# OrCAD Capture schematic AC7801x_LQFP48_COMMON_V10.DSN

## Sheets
1 POWER: size Custom; title: AC7801x_LQFP48_COMMON; rev: 1.0; company: Xinghui.Liu; note: POWER
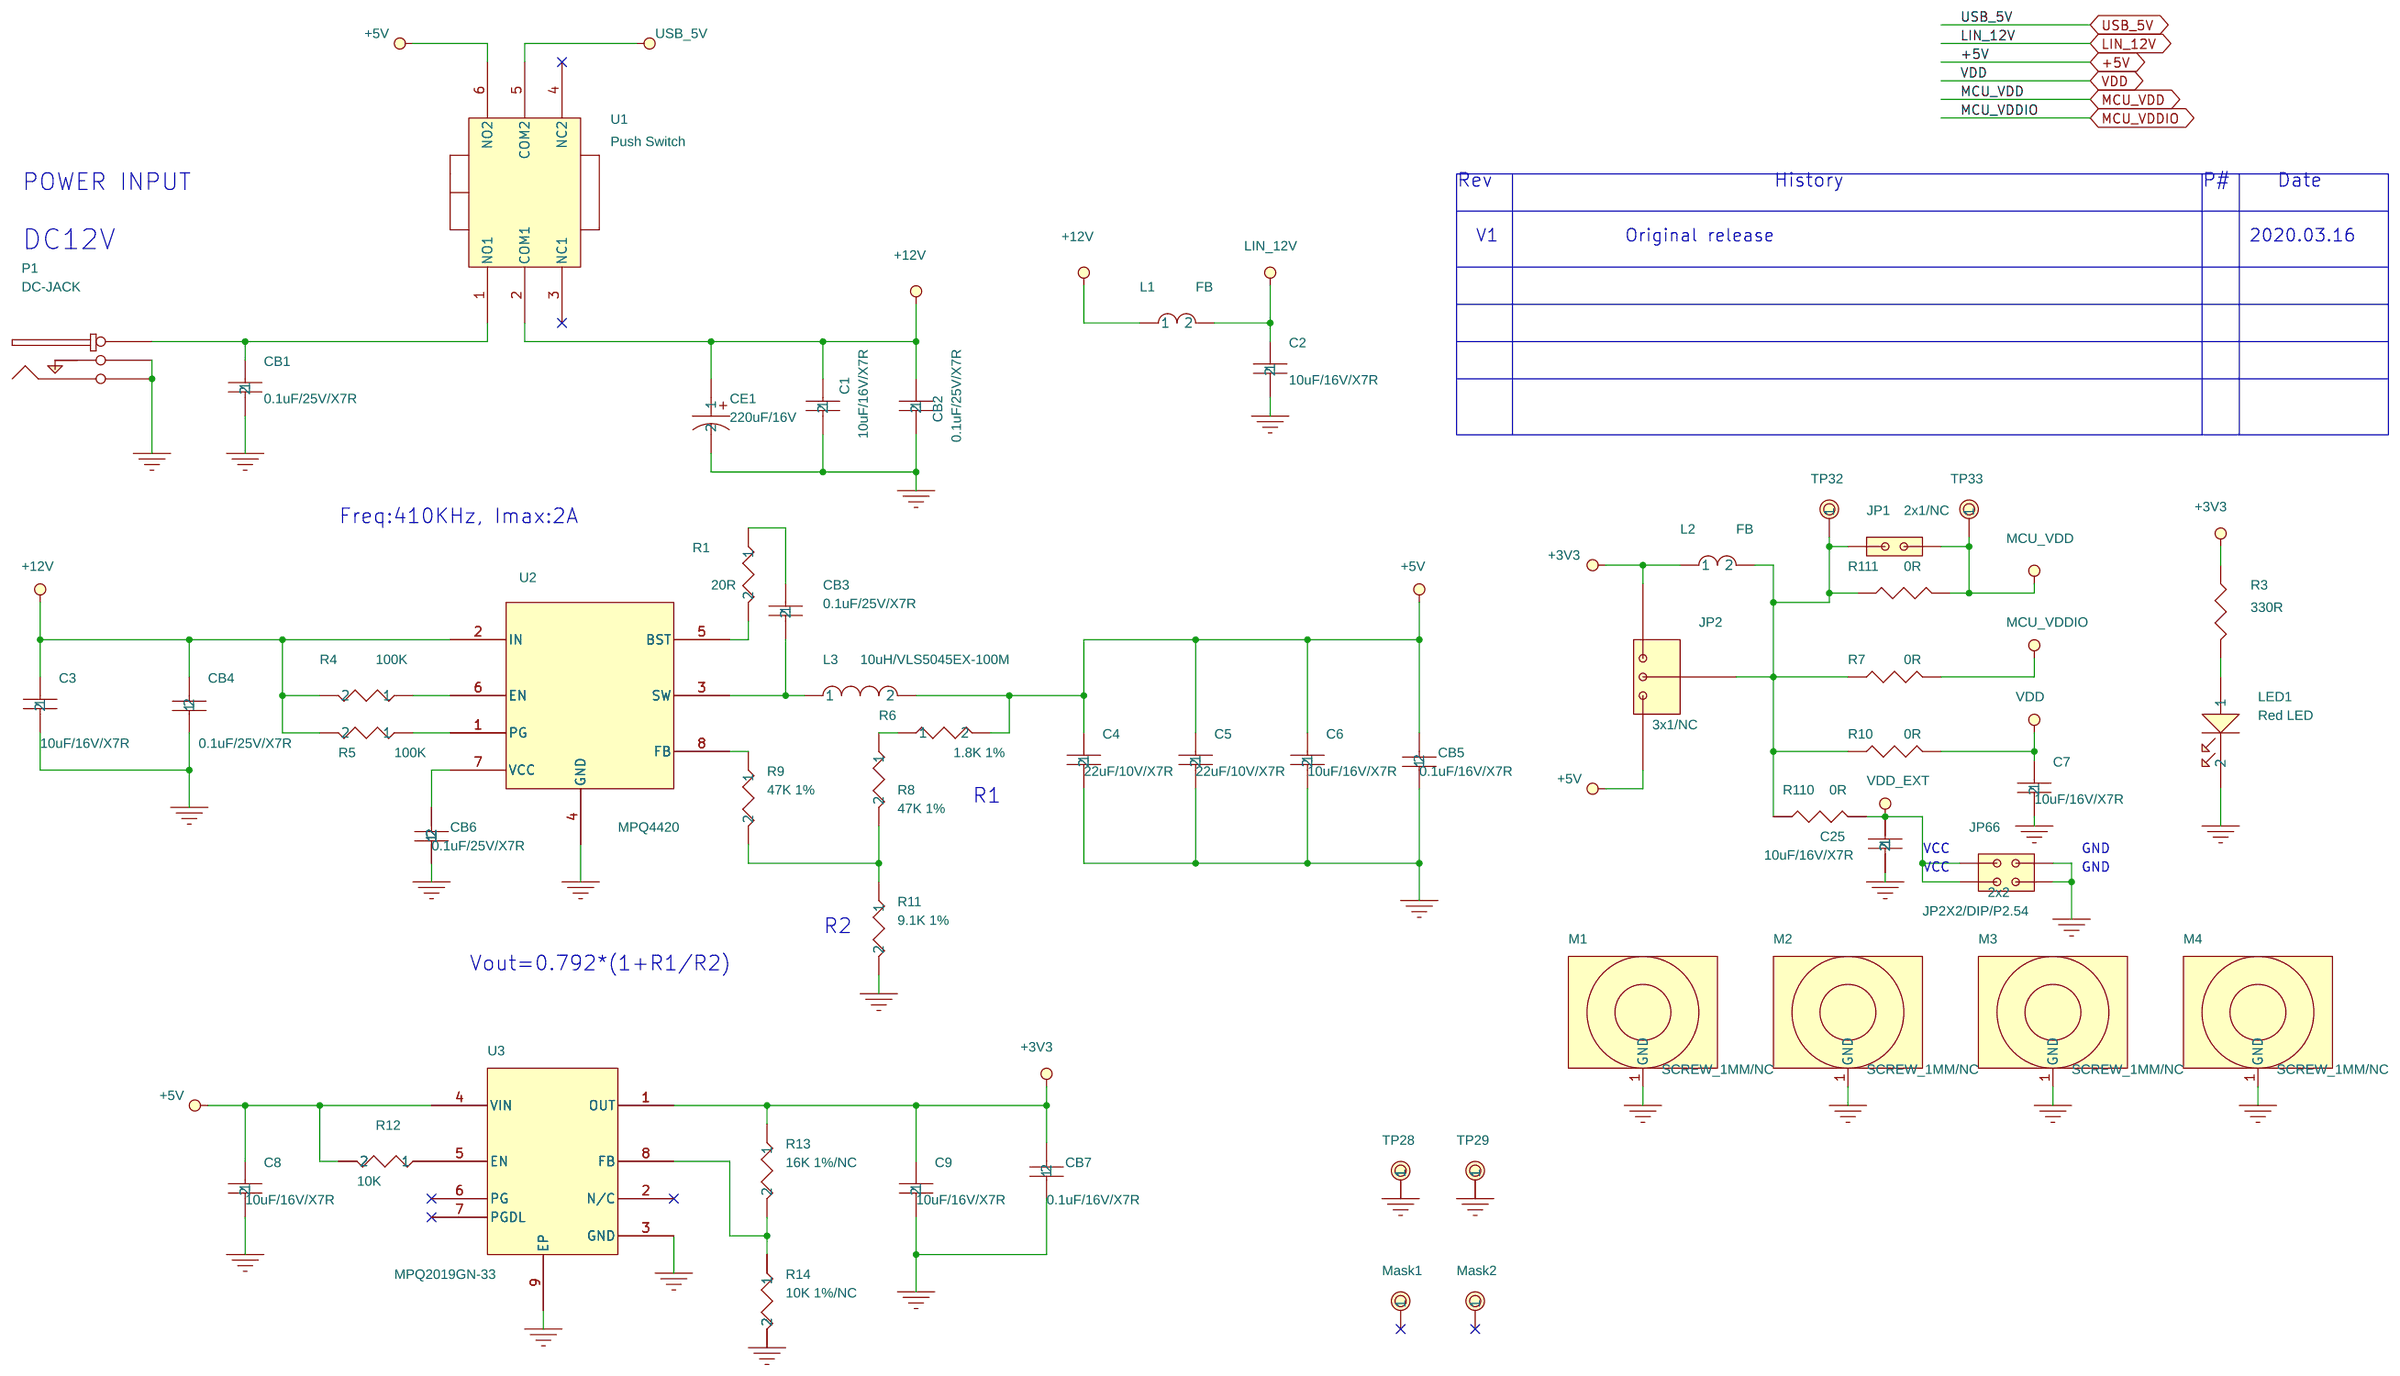
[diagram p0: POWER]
2 SYSTEM: size Custom; note: SYSTEM
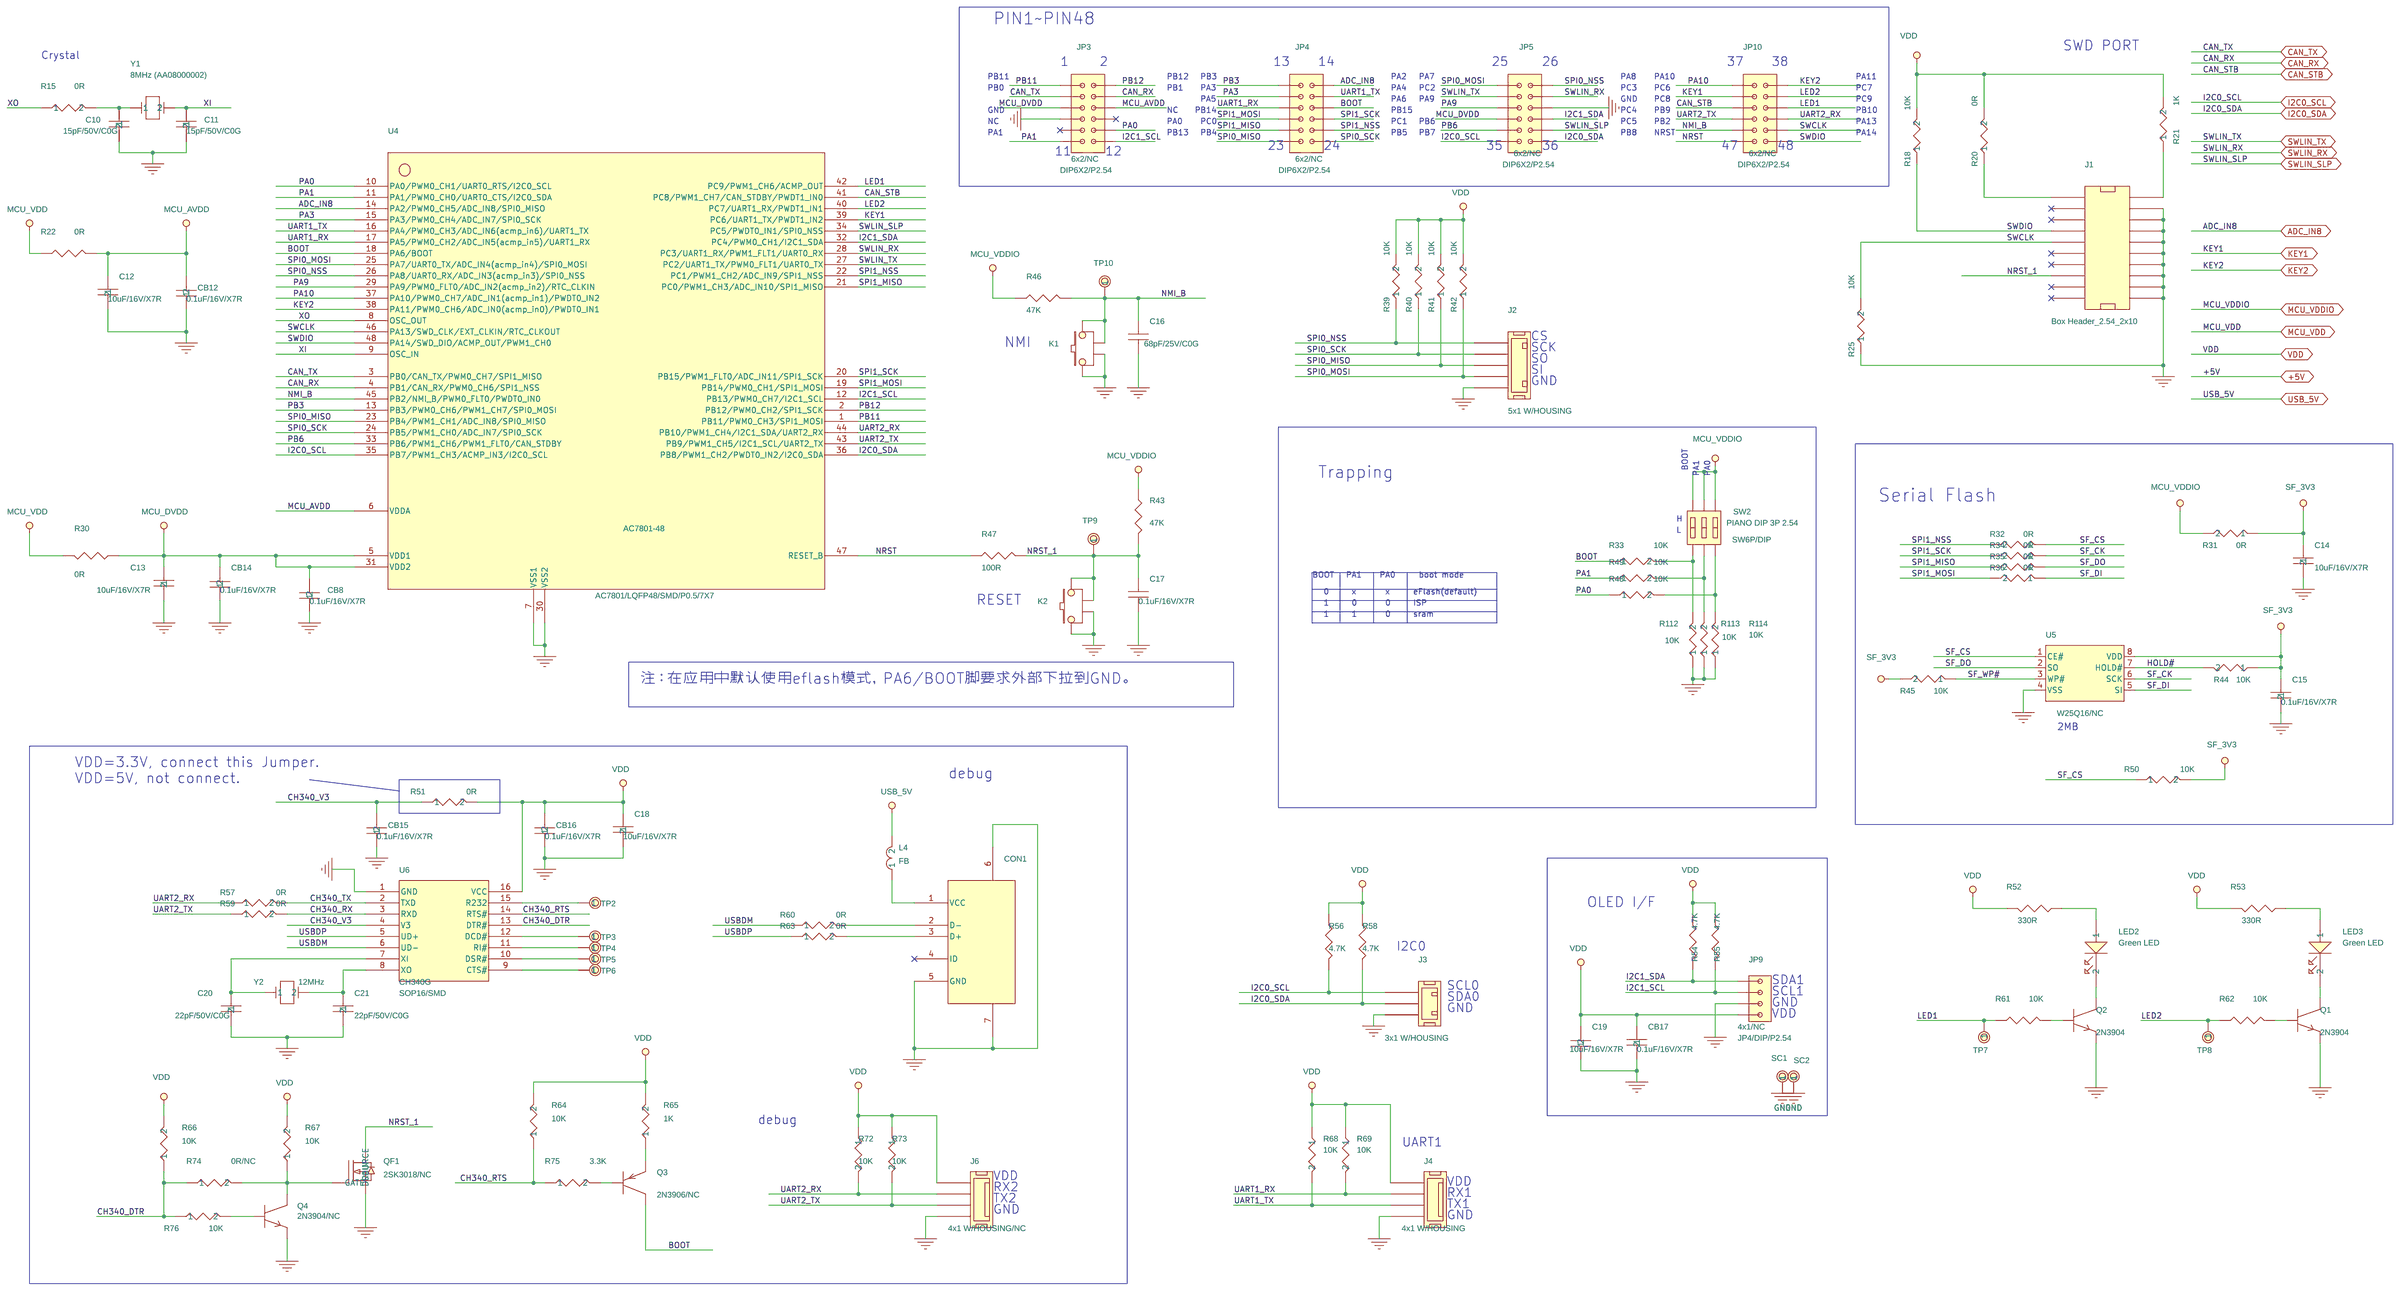
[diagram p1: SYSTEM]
3 CAN & LIN & KEY: size Custom; note: CAN & LIN & KEY
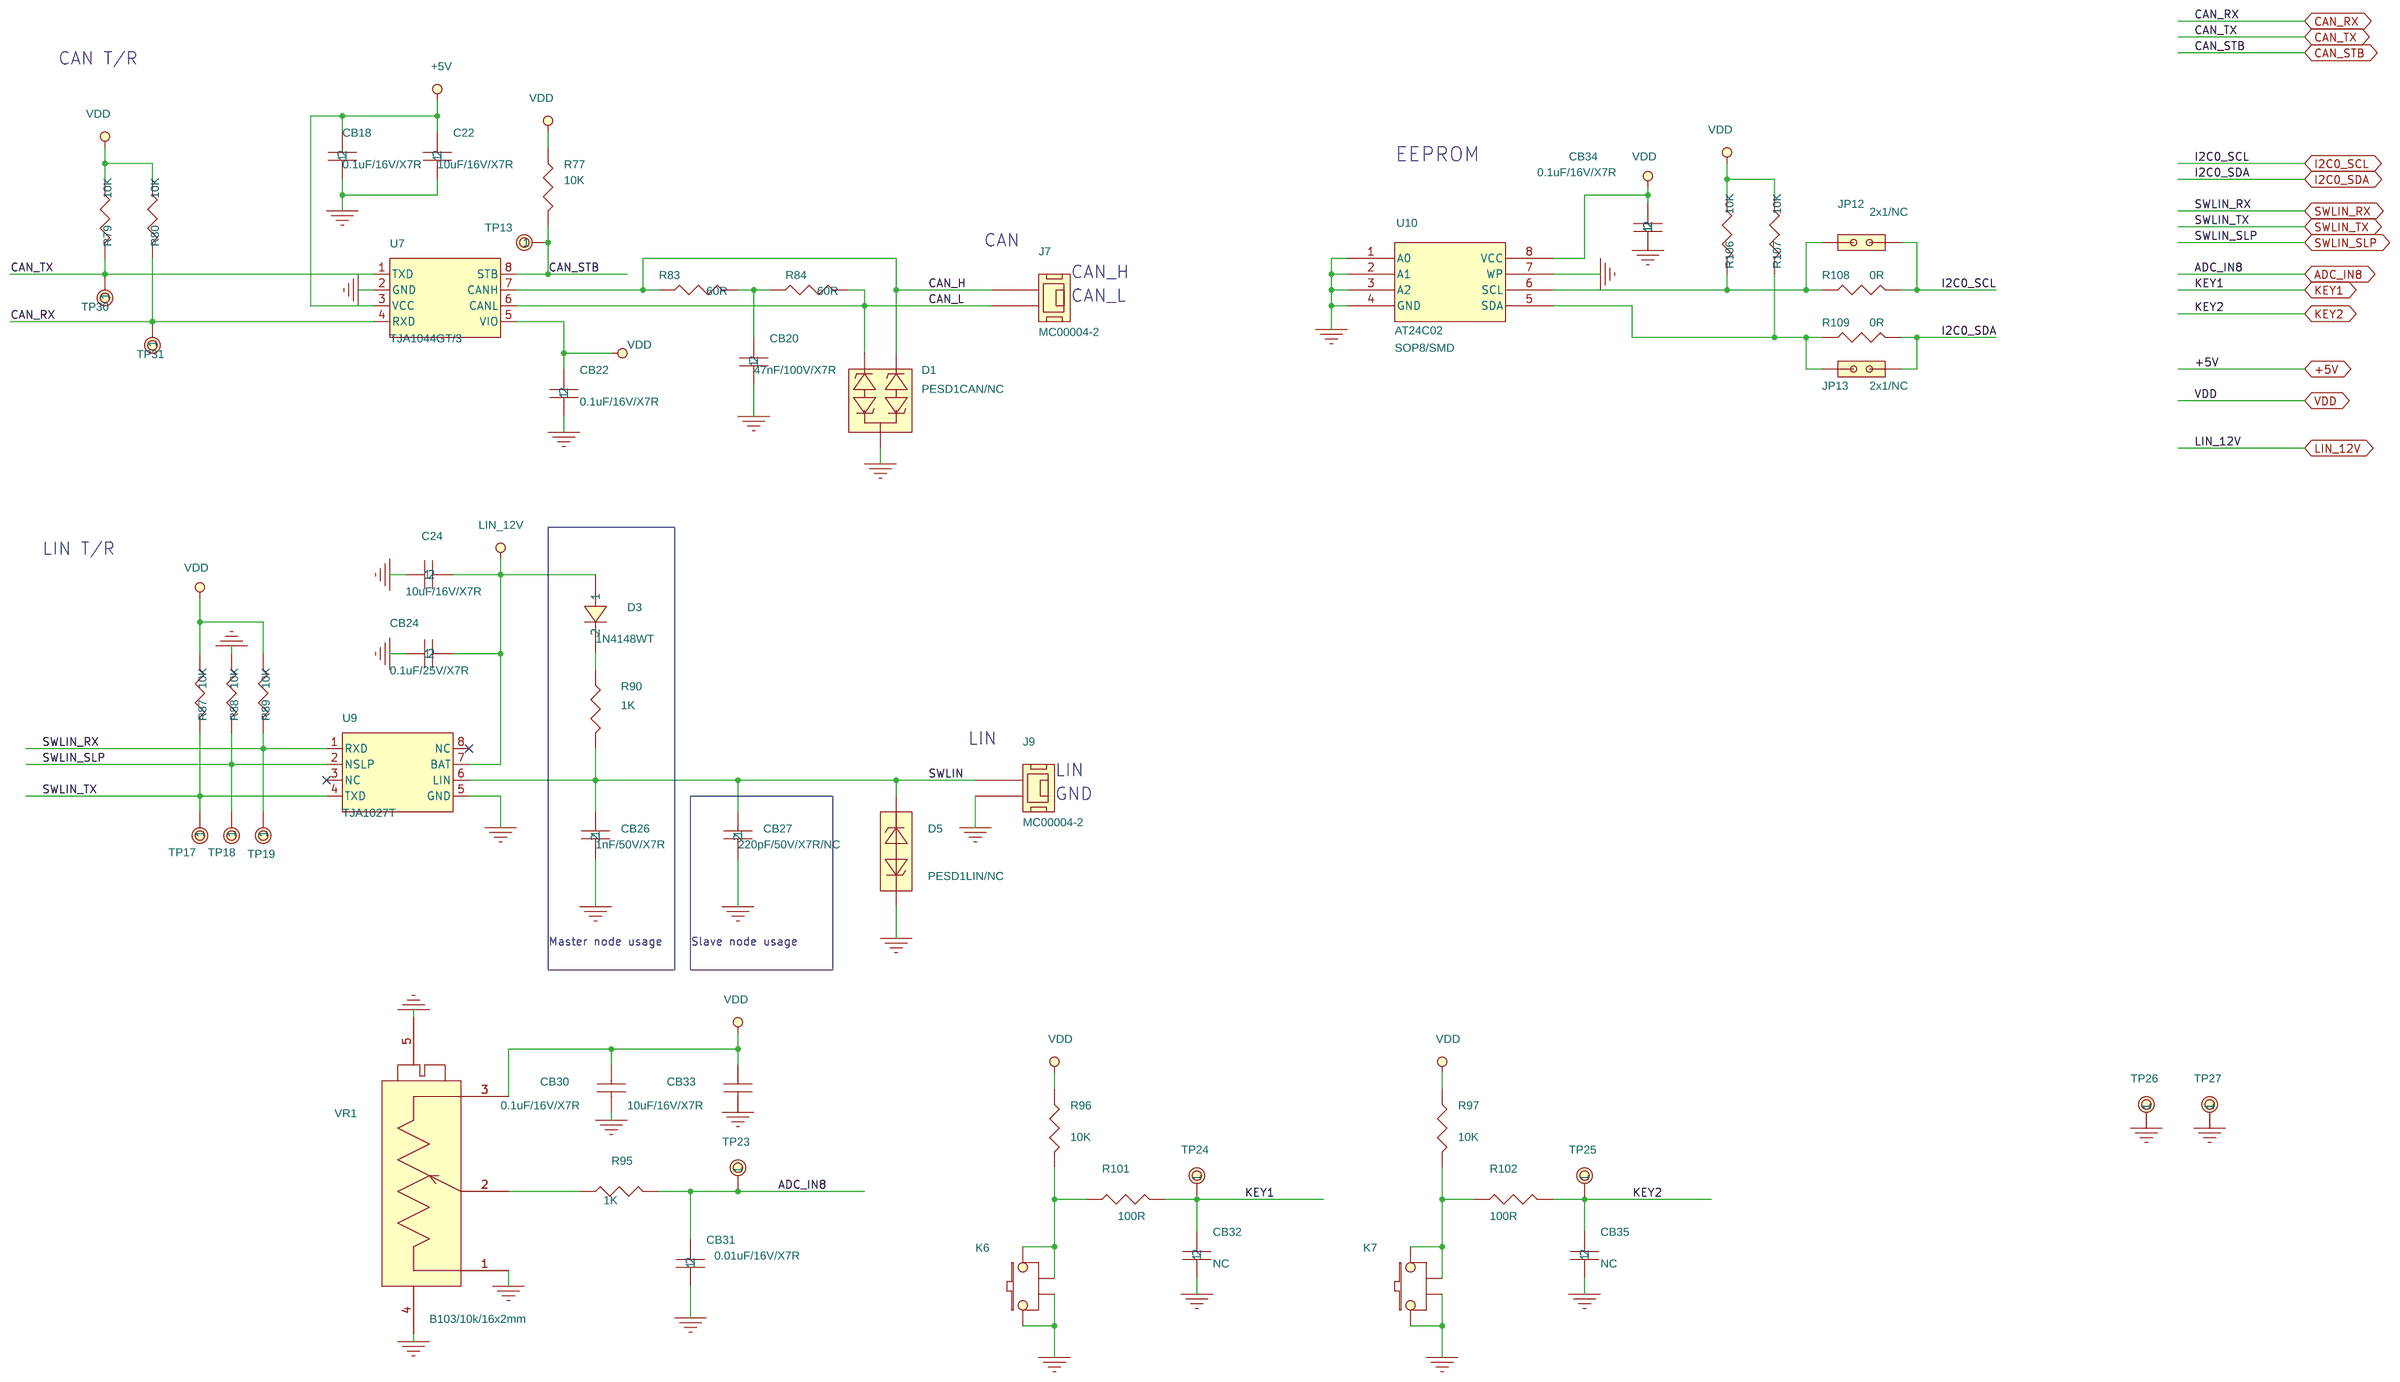
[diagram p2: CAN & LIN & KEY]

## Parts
sheet CAN & LIN & KEY
C22  10uF/16V/X7R  [C0805/SMD]
C24  10uF/16V/X7R  [C0805/SMD]
CB18  0.1uF/16V/X7R  [C0402/SMD]
CB20  47nF/100V/X7R  [C0603/SMD]
CB22  0.1uF/16V/X7R  [C0402/SMD]
CB24  0.1uF/25V/X7R  [C0402/SMD]
CB26  1nF/50V/X7R  [C0603/SMD]
CB27  220pF/50V/X7R/NC  [C0603/SMD]
CB30  0.1uF/16V/X7R  [C0402/SMD]
CB31  0.01uF/16V/X7R  [C0402/SMD]
CB32  NC  [C0402/SMD]
CB33  10uF/16V/X7R  [C0805/SMD]
CB34  0.1uF/16V/X7R  [C0402/SMD]
CB35  NC  [C0402/SMD]
D1  PESD1CAN/NC  [SOT23/SMD]
D3  1N4148WT  [D/SMD/1N4148WT]
D5  PESD1LIN/NC  [D/SMD/SOD323]
J7  MC00004-2  [PIN2_5.08MM_SCREW_TERMINAL]
J9  MC00004-2  [PIN2_5.08MM_SCREW_TERMINAL]
JP12  2x1/NC  [JP2/DIP/P2.54]
JP13  2x1/NC  [JP2/DIP/P2.54]
K6  SW  [KEY/SMD/3.2X4.2]
K7  SW  [KEY/SMD/3.2X4.2]
R77  10K  [R0603/SMD]
R79  10K  [R0603/SMD]
R80  10K  [R0603/SMD]
R83  60R  [R0603/SMD]
R84  60R  [R0603/SMD]
R87  10K  [R0603/SMD]
R88  10K  [R0603/SMD]
R89  10K  [R0603/SMD]
R90  1K  [R0603/SMD]
R95  1K  [R0603/SMD]
R96  10K  [R0603/SMD]
R97  10K  [R0603/SMD]
R101  100R  [R0603/SMD]
R102  100R  [R0603/SMD]
R106  10K  [R0603/SMD]
R107  10K  [R0603/SMD]
R108  0R  [R0603/SMD]
R109  0R  [R0603/SMD]
TP13  TEST POINT SMD1.0  [TP/SMD/D0.6]
TP17  TEST POINT SMD1.0  [TP/SMD/D0.6]
TP18  TEST POINT SMD1.0  [TP/SMD/D0.6]
TP19  TEST POINT SMD1.0  [TP/SMD/D0.6]
TP23  TEST POINT SMD1.0  [TP/SMD/D0.6]
TP24  TEST POINT SMD1.0  [TP/SMD/D0.6]
TP25  TEST POINT SMD1.0  [TP/SMD/D0.6]
TP26  TEST POINT SMD1.0/NC  [KEYSTONE5005]
TP27  TEST POINT SMD1.0/NC  [KEYSTONE5005]
TP30  TEST POINT SMD1.0  [TP/SMD/D0.6]
TP31  TEST POINT SMD1.0  [TP/SMD/D0.6]
U7  TJA1044GT/3  [SO8/SMD]
U9  TJA1027T  [SO8/SMD]
U10  AT24C02  [SOP8/SMD]
VR1  B103/10k/16x2mm  [SW/DIP5/16x2mm]
sheet POWER
C1  10uF/16V/X7R  [C0805/SMD]
C2  10uF/16V/X7R  [C0805/SMD]
C3  10uF/16V/X7R  [C0805/SMD]
C4  22uF/10V/X7R  [C0805/SMD]
C5  22uF/10V/X7R  [C0805/SMD]
C6  10uF/16V/X7R  [C0805/SMD]
C7  10uF/16V/X7R  [C0805/SMD]
C8  10uF/16V/X7R  [C0805/SMD]
C9  10uF/16V/X7R  [C0805/SMD]
C25  10uF/16V/X7R  [C0805/SMD]
CB1  0.1uF/25V/X7R  [C0402/SMD]
CB2  0.1uF/25V/X7R  [C0402/SMD]
CB3  0.1uF/25V/X7R  [C0402/SMD]
CB4  0.1uF/25V/X7R  [C0402/SMD]
CB5  0.1uF/16V/X7R  [C0402/SMD]
CB6  0.1uF/25V/X7R  [C0402/SMD]
CB7  0.1uF/16V/X7R  [C0402/SMD]
CE1  220uF/16V  [C100UF16V/SMD/D6H5]
JP1  2x1/NC  [JP2/DIP/P2.54]
JP2  3x1/NC  [JP3/DIP/P2.54]
JP66  2x2  [JP2X2/DIP/P2.54]
L1  FB  [BEAD/SMD/0805]
L2  FB  [BEAD/SMD/0805]
L3  10uH/VLS5045EX-100M  [L/CHOKE/SMD/LQH55DN2R2M03]
LED1  Red LED  [LED/SMD/0603]
M1  SCREW_1MM/NC  [SCREW_HOLE/PTH/R6.5D3.3]
M2  SCREW_1MM/NC  [SCREW_HOLE/PTH/R6.5D3.3]
M3  SCREW_1MM/NC  [SCREW_HOLE/PTH/R6.5D3.3]
M4  SCREW_1MM/NC  [SCREW_HOLE/PTH/R6.5D3.3]
Mask1  MARK POINT SMD1.0  [FD]
Mask2  MARK POINT SMD1.0  [FD]
P1  DC-JACK  [DC-JACK/6P/DIP/R/MD0881]
R1  20R  [R0603/SMD]
R3  330R  [R0603/SMD]
R4  100K  [R0603/SMD]
R5  100K  [R0603/SMD]
R6  1.8K 1%  [R0603/SMD]
R7  0R  [R0603/SMD]
R8  47K 1%  [R0603/SMD]
R9  47K 1%  [R0603/SMD]
R10  0R  [R0603/SMD]
R11  9.1K 1%  [R0603/SMD]
R12  10K  [R0603/SMD]
R13  16K 1%/NC  [R0603/SMD]
R14  10K 1%/NC  [R0603/SMD]
R110  0R  [R0603/SMD]
R111  0R  [R0603/SMD]
TP28  TEST POINT SMD1.0/NC  [KEYSTONE5005]
TP29  TEST POINT SMD1.0/NC  [KEYSTONE5005]
TP32  TEST POINT SMD1.0/NC  [KEYSTONE5005]
TP33  TEST POINT SMD1.0/NC  [KEYSTONE5005]
U1  Push Switch  [SW/6P/DIP/C3425/STEPBETTER]
U2  MPQ4420  [TSOT23-8/SMD/P0.65/MP2144]
U3  MPQ2019GN-33  [SOP8/SMD/EPAD]
sheet SYSTEM
C10  15pF/50V/C0G  [C0402/SMD]
C11  15pF/50V/C0G  [C0402/SMD]
C12  10uF/16V/X7R  [C0805/SMD]
C13  10uF/16V/X7R  [C0805/SMD]
C14  10uF/16V/X7R  [C0805/SMD]
C15  0.1uF/16V/X7R  [C0402/SMD]
C16  68pF/25V/C0G  [C0402/SMD]
C17  0.1uF/16V/X7R  [C0402/SMD]
C18  10uF/16V/X7R  [C0805/SMD]
C19  10uF/16V/X7R  [C0805/SMD]
C20  22pF/50V/C0G  [C0402/SMD]
C21  22pF/50V/C0G  [C0402/SMD]
CB8  0.1uF/16V/X7R  [C0402/SMD]
CB12  0.1uF/16V/X7R  [C0402/SMD]
CB14  0.1uF/16V/X7R  [C0402/SMD]
CB15  0.1uF/16V/X7R  [C0402/SMD]
CB16  0.1uF/16V/X7R  [C0402/SMD]
CB17  0.1uF/16V/X7R  [C0402/SMD]
CON1  Micro USB  [MICROUSB/5P/SMD/CNE004/LITKCONN]
J1  Box Header_2.54_2x10  [DIP10X2/W/H/IDE/P2.54]
J2  5x1 W/HOUSING  [DIP5/W/H/P2.54]
J3  3x1 W/HOUSING  [DIP3/W/H/P2.54]
J4  4x1 W/HOUSING  [DIP4/W/H/P2.0]
J6  4x1 W/HOUSING/NC  [DIP4/W/H/P2.0]
JP3  6x2/NC  [DIP6X2/P2.54]
JP4  6x2/NC  [DIP6X2/P2.54]
JP5  6x2/NC  [DIP6X2/P2.54]
JP9  4x1/NC  [JP4/DIP/P2.54]
JP10  6x2/NC  [DIP6X2/P2.54]
K1  SW  [KEY/SMD/3.2X4.2]
K2  SW  [KEY/SMD/3.2X4.2]
L4  FB  [BEAD/SMD/0805]
LED2  Green LED  [LED/SMD/0603]
LED3  Green LED  [LED/SMD/0603]
Q1  2N3904  [SOT23/SMD]
Q2  2N3904  [SOT23/SMD]
Q3  2N3906/NC  [SOT23/SMD]
Q4  2N3904/NC  [SOT23/SMD]
QF1  2SK3018/NC  [SOT23/SMD]
R15  0R  [R0603/SMD]
R18  10K  [R0603/SMD]
R20  0R  [R0603/SMD]
R21  1K  [R0603/SMD]
R22  0R  [R0603/SMD]
R25  10K  [R0603/SMD]
R30  0R  [R0603/SMD]
R31  0R  [R0603/SMD]
R32  0R  [R0603/SMD]
R33  10K  [R0603/SMD]
R34  0R  [R0603/SMD]
R35  0R  [R0603/SMD]
R36  0R  [R0603/SMD]
R39  10K  [R0603/SMD]
R40  10K  [R0603/SMD]
R41  10K  [R0603/SMD]
R42  10K  [R0603/SMD]
R43  47K  [R0603/SMD]
R44  10K  [R0603/SMD]
R45  10K  [R0603/SMD]
R46  47K  [R0603/SMD]
R47  100R  [R0603/SMD]
R48  10K  [R0603/SMD]
R49  10K  [R0603/SMD]
R50  10K  [R0603/SMD]
R51  0R  [R0603/SMD]
R52  330R  [R0603/SMD]
R53  330R  [R0603/SMD]
R54  4.7K  [R0603/SMD]
R55  4.7K  [R0603/SMD]
R56  4.7K  [R0603/SMD]
R57  0R  [R0603/SMD]
R58  4.7K  [R0603/SMD]
R59  0R  [R0603/SMD]
R60  0R  [R0603/SMD]
R61  10K  [R0603/SMD]
R62  10K  [R0603/SMD]
R63  0R  [R0603/SMD]
R64  10K  [R0603/SMD]
R65  1K  [R0603/SMD]
R66  10K  [R0603/SMD]
R67  10K  [R0603/SMD]
R68  10K  [R0603/SMD]
R69  10K  [R0603/SMD]
R72  10K  [R0603/SMD]
R73  10K  [R0603/SMD]
R74  0R/NC  [R0603/SMD]
R75  3.3K  [R0603/SMD]
R76  10K  [R0603/SMD]
R112  10K  [R0603/SMD]
R113  10K  [R0603/SMD]
R114  10K  [R0603/SMD]
SC1  TEST POINT SMD1.0  [OLED_HOLE_2_3.5MM]
SC2  TEST POINT SMD1.0  [OLED_HOLE_2_3.5MM]
SW2  PIANO DIP 3P 2.54  [SW6P/DIP]
TP2  TEST POINT SMD1.0  [TP/SMD/D0.6]
TP3  TEST POINT SMD1.0  [TP/SMD/D0.6]
TP4  TEST POINT SMD1.0  [TP/SMD/D0.6]
TP5  TEST POINT SMD1.0  [TP/SMD/D0.6]
TP6  TEST POINT SMD1.0  [TP/SMD/D0.6]
TP7  TEST POINT SMD1.0  [TP/SMD/D0.6]
TP8  TEST POINT SMD1.0  [TP/SMD/D0.6]
TP9  TEST POINT SMD1.0  [TP/SMD/D0.6]
TP10  TEST POINT SMD1.0  [TP/SMD/D0.6]
U4  AC7801-48  [AC7801/LQFP48/SMD/P0.5/7X7]
U5  W25Q16/NC  [SOIC8/SMD]
U6  CH340G  [SOP16/SMD]
Y1  8MHz (AA08000002)  [XTAL/SMD]
Y2  12MHz  [CRYS/SMD/49SM]

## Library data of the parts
C2 C22 = C0805_10uF_10v
C1 C24 = C0805_10uF_10v_1
CB18 = C0603_0.1uF_3
CB1 CB20 = C0603_0.1uF_1
CB22 = C0603_0.1uF_2
CB24 = C0603_0.1uF_4
CB7 CB15 CB26 = C0603_1
CB3 CB14 CB27 = C0603
C16 C17 CB30 CB33 = CAP_NP_0
CB31 = C0603_0.1uF_6
CB32 = C0603_0.1uF_7
CB2 CB34 = C0603_0.1uF
CB35 = C0603_0.1uF_5
D1 = DIODE__0: Function: HDMI Port2 ESD; Module: HDMI
D3 = DIODE_SMD
D5 = DIODE_SMD_0603_ESD_PROTECTION_1
J7 J9 = CONN_2_W_HOUSING_DIP_2.54
JP1 JP12 JP13 = JUMPER_2x1_DIP2.54
K1 K2 K6 K7 = SW_4P_SMD
R7 R10 R22 R30 R46 R47 R54-R56 R58 R77 R79 R80 R83 R84 R87-R90 R106-R111 = R_0
R3 R43 R52 R53 R61 R62 R95-R97 R101 R102 = RES
Mask1 Mask2 SC1 SC2 TP2-TP10 TP13 TP17-TP19 TP23-TP33 = TEST_POINT_SMD1.0
U7 = TJA1042_1
U9 = TJA1020_0
U10 = IC_EEPROM_24C16_SOP-8_1
VR1 = VR_3006P_DIP_3P_1
C3 = C1210_22uF_10v
C4 C13 = C0805_2: Function: VCCK_DC-DC
C5 C18 = C0805: Function: VCCK_DC-DC
C6 C14 = C0805_1: Function: VCCK_DC-DC
C7 = C1210_22uF_10v_4
C8 = C1210_22uF_10v_1
C9 = C1210_22uF_10v_2
C25 = C1210_22uF_10v_3
CB4 = C0603_3: Function: VCCK_DC-DC
C10 CB5 = C0603_4
C21 CB6 = C0603_2
CE1 = CAP_EC100uF_10v_D5H11
JP2 = JUMPER_3x1_DIP2_0.54
JP66 = JUMPER_3x2_DIP2_0.54
L1 = FERRITE_BEAD_SMD_0603_1
L2 L4 = FERRITE_BEAD_SMD_0603
L3 = INDUCTOR_CHOKE_DS1976_DU1311
LED1 LED3 = LED_DIP2.54
M1-M4 = SCREW_HOLE_3_0.5mm
P1 = PHONEJACK_0
R1 R63 = R0603_3
R4 R65 = R0603_6
R5 R31 = R0603_8
R6 R68 = R0603_5
R8 R36 = R0603_7
R9 R74 = R0603_2
R11 R39 = R0603_4
R12 R44 = R0603_1
R13 R41 = R0603_9
R14 R73 = R0603
U1 = Push_Switch_0
U2 = MPQ4420_0
U3 = G966A_1
C11 = C0603_7
C12 = C0805_4: Function: VCCK_DC-DC
C15 = C0603_10
C19 = C0805_3: Function: VCCK_DC-DC
C20 = C0603_8
CB8 = C0603_3
CB12 = C0603_5
CB16 = C0603_6
CB17 = C0603_9
CON1 = USB_JACK2_0
J1 = CONN_10x2_DIP_1.0
J2 = CONN_5_W_HOUSING_DIP_2.54
J3 = CONN_3_W_HOUSING_DIP_2.54
J4 J6 = CONN_4_W_HOUSING_DIP_2.0
JP3-JP5 JP10 = JUMPER_18x2_DIP2_0.54
JP9 = JUMPER_4x1_DIP2.54
LED2 = LED_DIP2.54_1
Q1 Q2 = TRANSISTOR_NPN_SMD(B-C-E): Function: HDMI Port2; Module: HDMI
Q3 = TRANSISTOR_PNP_SMD(B-C-E)
Q4 = TRANSISTOR_NPN_SMD(B-C-E)
QF1 = MOSFET_N_2N7002_SMD
R15 = R0603_23
R18 = R0603_16
R20 = R0603_35
R21 = R0603_20
R25 = R0603_19
R32 = R0603_26
R33 = R0603_18
R34 = R0603_33
R35 = R0603_15
R40 = R0603_25
R42 = R0603_31
R45 = R0603_10
R48 = R0603_37
R49 = R0603_11
R50 = R0603_38
R51 = R0603_34
R57 = R0603_32
R59 = R0603_14
R60 = R0603_21
R64 = R0603_24
R66 = R0603_29
R67 = R0603_13
R69 = R0603_28
R72 = R0603_22
R75 = R0603_17
R76 = R0603_36
R112 = R0603_12
R113 = R0603_30
R114 = R0603_27
SW2 = SW_PIANO_DIP_5P_2_0.54
U4 = AC7811_SMD_LQFP-80_14
U5 = SST25V040_serial_flash_0
U6 = CH340
Y1 = CRYSTAL_SMD_49SM
Y2 = CRYSTAL_SMD_49SM_1

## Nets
+3V3: C9.1 CB7.2 JP2.3 L2.1 R3.1 R13.1 U3.1(OUT)
+5V: C4.1 C5.1 C6.1 C8.1 C22.2 CB5.2 CB18.2 JP2.1 L3.2 R6.2 R12.2 U1.6(NO2) U3.4(VIN) U7.3(VCC)
+12V: C1.1 C3.1 CB2.1 CB4.2 CE1.1 L1.1 R4.2 R5.2 U1.2(COM1) U2.2(IN)
GND: C1.2 C2.2 C3.2 C4.2 C5.2 C6.2 C7.2 C8.2 C9.2 C10.2 C11.2 C12.2 C13.2 C14.2 C15.2 C16.2 C17.2 C18.2 C19.1 C20.2 C21.2 C22.1 C24.1 C25.2 CB1.2 CB2.2 CB4.1 CB5.1 CB6.1 CB7.1 CB8.1 CB12.1 CB14.1 CB15.1 CB16.1 CB17.2 CB18.1 CB20.1 CB22.1 CB24.1 CB26.2 CB27.2 CB30.2 CB31.1 CB32.1 CB33.2 CB34.1 CB35.1 CE1.2 CON1.5(GND) CON1.6 CON1.7 D1.2 D5.2 J1.4 J1.6 J1.8 J1.10 J1.12 J1.14 J1.16 J1.18 J1.20 J2.5 J3.3 J4.4 J6.4 J9.1 JP3.7 JP5.6 JP9.2 JP66.2 JP66.4 K1.1 K1.2 K2.1 K2.2 K6.1 K6.2 K7.1 K7.2 LED1.2 M1.1(GND) M2.1(GND) M3.1(GND) M4.1(GND) P1.2 P1.3 Q1.3 Q2.3 Q4.3 QF1.3(SOURCE) R11.2 R14.2 R25.1 R88.2 R112.1 R113.1 R114.1 SC1.1 SC2.1 TP26.1 TP27.1 TP28.1 TP29.1 U2.4(GND) U3.3(GND) U3.9(EP) U4.7(VSS1) U4.30(VSS2) U5.4(VSS) U6.1(GND) U7.2(GND) U9.5(GND) U10.1(A0) U10.2(A1) U10.3(A2) U10.4(GND) U10.7(WP) VR1.1 VR1.4 VR1.5
VDD: C7.1 C18.1 C19.2 CB16.2 CB17.1 CB22.2 CB30.1 CB33.1 CB34.2 J4.1 J6.1 JP9.1 R10.1 R18.2 R20.2 R21.2 R39.2 R40.2 R41.2 R42.2 R51.2 R52.2 R53.2 R54.2 R55.2 R56.2 R58.2 R64.2 R65.2 R66.2 R67.2 R68.1 R69.1 R72.1 R73.1 R77.2 R79.2 R80.2 R87.2 R89.2 R96.1 R97.1 R106.2 R107.2 U6.16(VCC) U7.5(VIO) U10.8(VCC) VR1.3
VDD_EXT: C25.1 JP66.1 JP66.3 R110.1
ADC_IN8: CB31.2 JP4.2 R95.2 TP23.1 U4.14(PA2/PWM0_CH5/ADC_IN8/SPI0_MISO)
BOOT: JP4.6 Q3.2 R33.1 U4.18(PA6/BOOT)
CAN_H: D1.1 J7.2 R83.2 U7.7(CANH)
CAN_L: D1.3 J7.1 R84.1 U7.6(CANL)
CAN_RX: JP3.4 R80.1 TP31.1 U4.4(PB1/CAN_RX/PWM0_CH6/SPI1_NSS) U7.4(RXD)
CAN_STB: JP10.5 R77.1 TP13.1 U4.41(PC8/PWM1_CH7/CAN_STDBY/PWDT1_IN0) U7.8(STB)
CAN_TX: JP3.3 R79.1 TP30.1 U4.3(PB0/CAN_TX/PWM0_CH7/SPI1_MISO) U7.1(TXD)
CH340_DTR: R66.1 R74.1 R76.1 U6.13(DTR#)
CH340_RTS: R64.1 R75.1 U6.14(RTS#)
CH340_RX: R59.2 U6.3(RXD)
CH340_TX: R57.2 U6.2(TXD)
CH340_V3: CB15.2 R51.1 U6.4(V3)
HOLD#: R44.2 U5.7(HOLD#)
I2C0_SCL: J3.1 JP5.11 JP12.2 R56.1 R108.1 U4.35(PB7/PWM1_CH3/ACMP_IN3/I2C0_SCL)
I2C0_SDA: J3.2 JP5.12 JP13.2 R58.1 R109.1 U4.36(PB8/PWM1_CH2/PWDT0_IN2/I2C0_SDA)
I2C1_SCL: JP3.12 JP9.3 R55.1 U4.12(PB13/PWM0_CH7/I2C1_SCL)
I2C1_SDA: JP5.8 JP9.4 R54.1 U4.32(PC4/PWM0_CH1/I2C1_SDA)
KEY1: CB32.2 JP10.3 R101.2 TP24.1 U4.39(PC6/UART1_TX/PWDT1_IN2)
KEY2: CB35.2 JP10.2 R102.2 TP25.1 U4.38(PA11/PWM0_CH6/ADC_IN0(acmp_in0)/PWDT0_IN1)
LED1: JP10.6 R61.1 TP7.1 U4.42(PC9/PWM1_CH6/ACMP_OUT)
LED2: JP10.4 R62.1 TP8.1 U4.40(PC7/UART1_RX/PWDT1_IN1)
LIN_12V: C2.1 C24.2 CB24.2 D3.1 L1.2 U9.7(BAT)
MCU_AVDD: C12.1 CB12.2 JP3.6 R22.1 U4.6(VDDA)
MCU_DVDD: C13.1 CB8.2 CB14.2 JP3.5 JP5.7 R30.2 U4.5(VDD1) U4.31(VDD2)
MCU_VDD: JP1.2 R22.2 R30.1 R111.1 TP33.1
MCU_VDDIO: R7.1 R31.2 R43.1 R46.2 SW2.1 SW2.3 SW2.5
NMI_B: C16.1 JP10.9 K1.3 K1.4 R46.1 TP10.1 U4.45(PB2/NMI_B/PWM0_FLT0/PWDT0_IN0)
NRST: JP10.11 R47.2 U4.47(RESET_B)
NRST_1: C17.1 J1.15 K2.3 K2.4 QF1.2(DRAIN) R43.2 R47.1 TP9.1
PA0: JP3.10 R48.1 U4.10(PA0/PWM0_CH1/UART0_RTS/I2C0_SCL)
PA1: JP3.11 R49.1 U4.11(PA1/PWM0_CH0/UART0_CTS/I2C0_SDA)
PA3: JP4.3 U4.15(PA3/PWM0_CH4/ADC_IN7/SPI0_SCK)
PA9: JP5.5 U4.29(PA9/PWM0_FLT0/ADC_IN2(acmp_in2)/RTC_CLKIN)
PA10: JP10.1 U4.37(PA10/PWM0_CH7/ADC_IN1(acmp_in1)/PWDT0_IN2)
PB3: JP4.1 U4.13(PB3/PWM0_CH6/PWM1_CH7/SPI0_MOSI)
PB6: JP5.9 U4.33(PB6/PWM1_CH6/PWM1_FLT0/CAN_STDBY)
PB11: JP3.1 U4.1(PB11/PWM0_CH3/SPI1_MOSI)
PB12: JP3.2 U4.2(PB12/PWM0_CH2/SPI1_SCK)
SF_3V3: C14.1 C15.1 R31.1 R44.1 R45.2 R50.2 U5.8(VDD)
SF_CK: R34.1 U5.6(SCK)
SF_CS: R32.1 R50.1 U5.1(CE#)
SF_DI: R36.1 U5.5(SI)
SF_DO: R35.1 U5.2(SO)
SF_WP#: R45.1 U5.3(WP#)
SPI0_MISO: J2.3 JP4.11 R41.1 U4.23(PB4/PWM1_CH1/ADC_IN8/SPI0_MISO)
SPI0_MOSI: J2.4 JP5.1 R42.1 U4.25(PA7/UART0_TX/ADC_IN4(acmp_in4)/SPI0_MOSI)
SPI0_NSS: J2.1 JP5.2 R39.1 U4.26(PA8/UART0_RX/ADC_IN3(acmp_in3)/SPI0_NSS)
SPI0_SCK: J2.2 JP4.12 R40.1 U4.24(PB5/PWM1_CH0/ADC_IN7/SPI0_SCK)
SPI1_MISO: JP4.9 R35.2 U4.21(PC0/PWM1_CH3/ADC_IN10/SPI1_MISO)
SPI1_MOSI: JP4.7 R36.2 U4.19(PB14/PWM0_CH1/SPI1_MOSI)
SPI1_NSS: JP4.10 R32.2 U4.22(PC1/PWM1_CH2/ADC_IN9/SPI1_NSS)
SPI1_SCK: JP4.8 R34.2 U4.20(PB15/PWM1_FLT0/ADC_IN11/SPI1_SCK)
SWCLK: J1.9 JP10.10 R25.2 U4.46(PA13/SWD_CLK/EXT_CLKIN/RTC_CLKOUT)
SWDIO: J1.7 JP10.12 R18.1 U4.48(PA14/SWD_DIO/ACMP_OUT/PWM1_CH0)
SWLIN: CB26.1 CB27.1 D5.1 J9.2 R90.1 U9.6(LIN)
SWLIN_RX: JP5.4 R89.1 TP19.1 U4.28(PC3/UART1_RX/PWM1_FLT1/UART0_RX) U9.1(RXD)
SWLIN_SLP: JP5.10 R88.1 TP18.1 U4.34(PC5/PWDT0_IN1/SPI0_NSS) U9.2(NSLP)
SWLIN_TX: JP5.3 R87.1 TP17.1 U4.27(PC2/UART1_TX/PWM0_FLT1/UART0_TX) U9.4(TXD)
UART1_RX: J4.2 JP4.5 R69.2 U4.17(PA5/PWM0_CH2/ADC_IN5(acmp_in5)/UART1_RX)
UART1_TX: J4.3 JP4.4 R68.2 U4.16(PA4/PWM0_CH3/ADC_IN6(acmp_in6)/UART1_TX)
UART2_RX: J6.2 JP10.8 R57.1 R72.2 U4.44(PB10/PWM1_CH4/I2C1_SDA/UART2_RX)
UART2_TX: J6.3 JP10.7 R59.1 R73.2 U4.43(PB9/PWM1_CH5/I2C1_SCL/UART2_TX)
USB_5V: L4.2 U1.5(COM2)
USBDM: R60.1 U6.6(UD-)
USBDP: R63.1 U6.5(UD+)
XI: C11.1 U4.9(OSC_IN) Y1.2
XO: R15.1 U4.8(OSC_OUT)
N19976186: CB20.2 R83.1 R84.2
N20023720: C10.1 R15.2 Y1.1
N20048702: R8.2 R9.2 R11.1
N20048714: R4.1 U2.6(EN)
N20048874: R5.1 U2.1(PG)
N20048896: CB6.2 U2.7(VCC)
N20048923: R9.1 U2.8(FB)
N20049299: R6.1 R8.1
N20049327: CB3.2 L3.1 U2.3(SW)
N20049347: R1.2 U2.5(BST)
N20049351: CB3.1 R1.1
N20300623: LED1.1 R3.2
N20421303: D3.2 R90.2
N20522720: R13.2 R14.1 U3.8(FB)
N20531899: JP1.1 JP2.2 L2.2 R7.2 R10.2 R110.2 R111.2 TP32.1
N20533279: LED3.1 R53.1
N20533292: LED3.2 Q1.2
N20533315: Q1.1 R62.2
N20533474: LED2.1 R52.1
N20533487: LED2.2 Q2.2
N20533510: Q2.1 R61.2
N20638518: CB1.1 P1.1 U1.1(NO1)
N20642912: R33.2 R112.2 SW2.6
N20645186: TP2.1 U6.15(R232)
N20645246: CON1.2(D-) R60.2
N20645251: TP3.1 U6.12(DCD#)
N20645263: CON1.3(D+) R63.2
N20645268: TP4.1 U6.11(RI#)
N20645281: C20.1 U6.7(XI) Y2.1
N20645285: TP5.1 U6.10(DSR#)
N20645294: C21.1 U6.8(XO) Y2.2
N20645298: TP6.1 U6.9(CTS#)
N20645437: Q3.3 R65.1
N20645450: Q4.2 QF1.1(GATE) R67.1 R74.2
N20645488: Q3.1 R75.2
N20645514: Q4.1 R76.2
N20646473: J1.1 R20.1
N20646475: J1.2 R21.1
N20658738: CON1.1(VCC) L4.1
N20677725: K6.3 K6.4 R96.2 R101.1
N20811438: R95.1 VR1.2
N20812935: JP12.1 R106.1 R108.2 U10.6(SCL)
N20812942: JP13.1 R107.1 R109.2 U10.5(SDA)
N20817593: K7.3 K7.4 R97.2 R102.1
N20879681: R49.2 R113.2 SW2.4
N20880606: R48.2 R114.2 SW2.2
N20903126: R12.1 U3.5(EN)

Not connected (* = marked no-connect by the designer): CON1 4(ID)*; J1 3* 5* 11* 13* 17* 19*; JP3 8* 9*; Mask1 1*; Mask2 1*; U1 3(NC1)* 4(NC2)*; U3 2(N/C)* 6(PG)* 7(PGDL)*; U9 3(NC)* 8(NC)*

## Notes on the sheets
sheet 1
- POWER INPUT
- Rev
- History
- P#
- Date
- DC12V
- V1
- Original release
- 2020.03.16
- Freq:410KHz, Imax:2A
- R1
- VCC
- GND
- VCC
- GND
- R2
- Vout=0.792*(1+R1/R2)
sheet 2
- PIN1~PIN48
- Crystal
- SWD PORT
- 1
- 2
- 13
- 14
- 25
- 26
- 37
- 38
- PB11
- PB12
- PB3
- PA2
- PA7
- PA8
- PA10
- PA11
- PB0
- PB1
- PA3
- PA4
- PC2
- PC3
- PC6
- PC7
- PA5
- PA6
- PA9
- GND
- PC8
- PC9
- GND
- NC
- PB14
- PB15
- PC4
- PB9
- PB10
- NC
- PA1
- PA0
- PB13
- PB4
- PC0
- PB5
- PC1
- PB6
- PB7
- PB8
- PC5
- NRST
- PB2
- PA13
- PA14
- 23
- 24
- 35
- 36
- 47
- 48
- 11
- 12
- NMI
- CS
- SCK
- SO
- SI
- GND
- Trapping
- BOOT
- PA1
- PA0
- Serial Flash
- H
- L
- BOOT
- PA1
- PA0
- boot mode
- 0
- x
- x
- eFlash(default)
- RESET
- 1
- 0
- 0
- ISP
- 1
- 1
- 0
- sram
- 注：在应用中默认使用eflash模式，PA6/BOOT脚要求外部下拉到GND。
- 2MB
- VDD=3.3V, connect this Jumper.
  VDD=5V, not connect.
- debug
- OLED I/F
- I2C0
- SDA1
- SCL0
- SCL1
- GND
- SDA0
- GND
- VDD
- debug
- UART1
- VDD
- RX2
- RX1
- VDD
- TX2
- TX1
- GND
- GND
sheet 3
- CAN T/R
- EEPROM
- CAN
- CAN_H
- CAN_L
- LIN T/R
- LIN
- LIN
- GND
- Master node usage
- Slave node usage
